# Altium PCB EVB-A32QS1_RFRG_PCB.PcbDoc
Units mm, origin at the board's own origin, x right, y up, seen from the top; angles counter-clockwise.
Board outline 152.4 x 101.6 mm, 4 copper layers (L1 (Signal), L2 (GND), L3 (GND), L4 (Signal)), stack 1.586 mm thick; 35 components, 27 nets, 136 pads, 0 vias.
Unrouted connection lines stored in the file: 88.
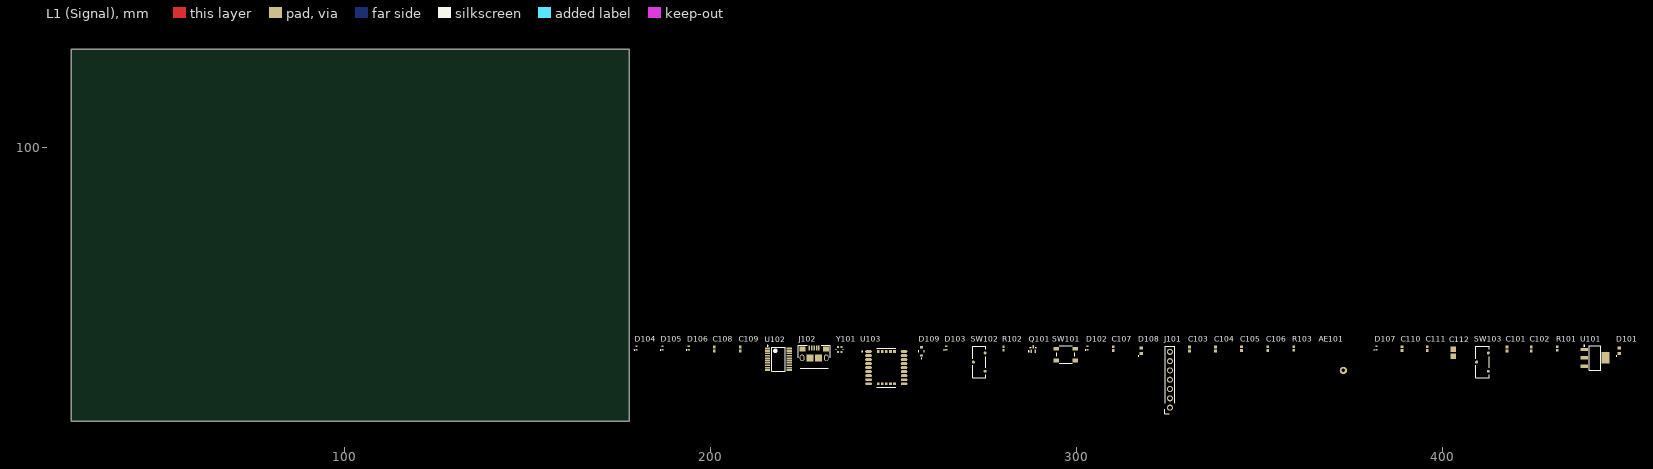
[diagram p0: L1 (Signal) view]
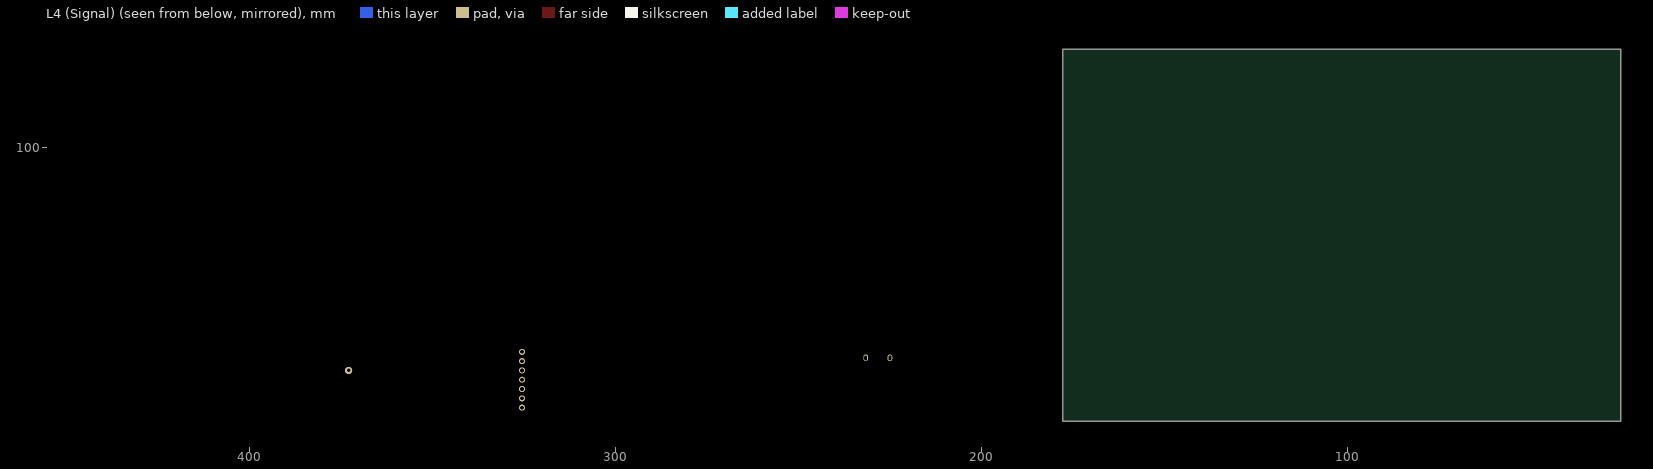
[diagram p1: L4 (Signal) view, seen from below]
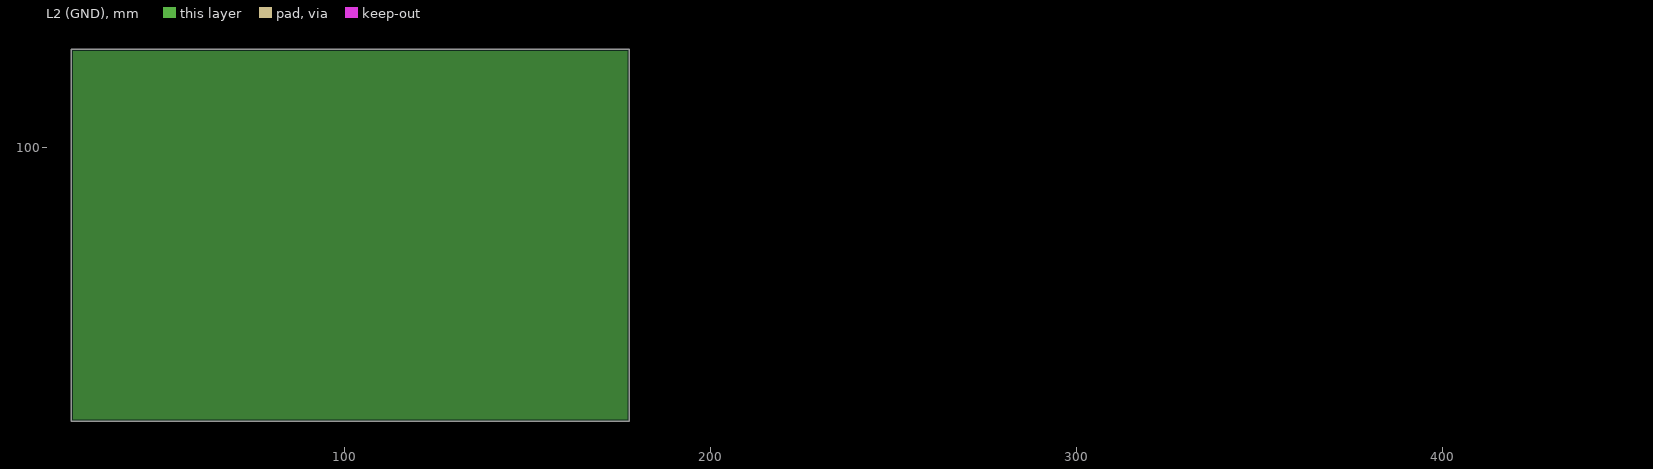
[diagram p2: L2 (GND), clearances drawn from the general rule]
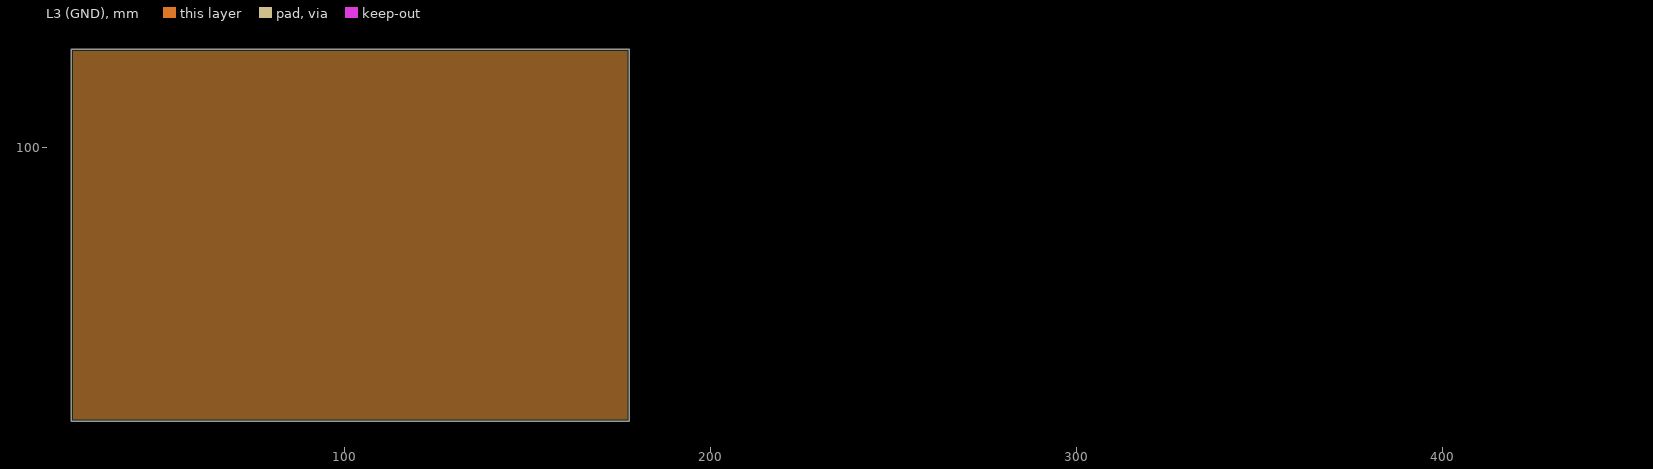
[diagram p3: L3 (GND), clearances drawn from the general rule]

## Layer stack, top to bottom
Top Solder: solder mask 0.0152, JLC-001, Dk 3.8
L1 (Signal): signal copper 0.035
PP1_7628: prepreg 0.2104, Nan Ya Plastics NP-155F 7628, Dk 4.4
L2 (GND): plane copper 0.0152
C_FR4: core 1.065, Nan Ya Plastics NP-155F FR4 / 1-7628, Dk 4.6
L3 (GND): plane copper 0.0152
PP2_7628: prepreg 0.2104, Nan Ya Plastics NP-155F 7628, Dk 4.4
L4 (Signal): signal copper 0.035
Bottom Solder: solder mask 0.0152, JLC-001, Dk 3.8

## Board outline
25.4,25.4 177.8,25.4 177.8,127 25.4,127

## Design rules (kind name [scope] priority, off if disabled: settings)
BoardOutlineClearance [IsText = 'True'] p1: gap=0.3 ignorepadtopadclearanceinfootprint=FALSE
Clearance [All] p1: gap=0.25 ignorepadtopadclearanceinfootprint=FALSE except(0.1: Arc-Arc Arc-Track Track-Track; 0.15: SMDPad-SMDPad; 0.22: Arc-SMDPad Track-SMDPad; 0.27: Arc-Via Arc-Hole Track-Via Track-Hole; 0.5: THPad-THPad)
DiffPairsRouting [InDifferentialPairClass('DIFF_USB')] p1: maxlimit=0.203 minlimit=0.203 mostfreqgap=0.203 toplayer_minwidth=0.286 toplayer_maxwidth=0.286 toplayer_prefwidth=0.286 bottomlayer_minwidth=0.286 bottomlayer_maxwidth=0.286 bottomlayer_prefwidth=0.286 impedanceprofiledriven=TRUE impedanceprofileid={1D80E4EB-765F-47FF-8A09-11E6335E2081} impedanceprofilevalue=90.000000 maxuncoupledlength=12.7
HoleSize NPTHSlotSize [HoleType = 'Slot' && PadIsPlated = 'False'] p1: absolutevalues=TRUE maxlimit=5.6 minlimit=1 maxpercent=80.000 minpercent=20.000
HoleSize PTHSlotSize [HoleType = 'Slot' && PadIsPlated = 'True'] p2: absolutevalues=TRUE maxlimit=5.6 minlimit=0.5 maxpercent=80.000 minpercent=20.000
HoleSize PTHSize [PadIsPlated = 'True'] p3: absolutevalues=TRUE maxlimit=6.35 minlimit=0.2 maxpercent=80.000 minpercent=20.000
HoleSize NPTHSize [PadIsPlated = 'False'] p4: absolutevalues=TRUE maxlimit=6.3 minlimit=0.2 maxpercent=80.000 minpercent=20.000
HoleToHoleClearance [All] p1: gap=0.5 allowstackedmicrovias=TRUE
MinimumAnnularRing PTHSlotMinimumAnnularRing_1 [HoleType = 'Slot' && PadIsPlated = 'True'] p1: minimumring=0.3
MinimumAnnularRing PTHMinimumAnnularRing [PadIsPlated = 'True'] p2: minimumring=0.3
MinimumAnnularRing ViaMinimumAnnularRing [IsVia] p3: minimumring=0.15
MinimumSolderMaskSliver [All] p1: minsoldermaskwidth=0.1
PlaneClearance [All] p1: clearance=0.508
PlaneConnect [All] p1: pad.planeconnectstyle=Relief pad.reliefexpansion=0.508 pad.reliefentries=4 pad.reliefconductorwidth=0.254 pad.reliefairgap=0.254 via.planeconnectstyle=Direct via.reliefexpansion=0.508 via.reliefentries=4 via.reliefconductorwidth=0.254 via.reliefairgap=0.254
PolygonConnect [All] p1: thpad.connectstyle=Relief thpad.reliefconductorwidth=0.254 thpad.reliefentries=4 thpad.polygonreliefangle="90 Angle" thpad.airgapwidth=0.254 smdpad.connectstyle=Relief smdpad.reliefconductorwidth=0.254 smdpad.reliefentries=4 smdpad.polygonreliefangle="90 Angle" smdpad.airgapwidth=0.254 via.connectstyle=Direct via.reliefconductorwidth=0.254 via.reliefentries=4 via.polygonreliefangle="90 Angle" via.airgapwidth=0.254
RoutingVias [All] p1: holewidth=0.3 width=0.7 viastyle="Through Hole" minholewidth=0.2 minwidth=0.5 maxholewidth=0.5 maxwidth=1
SilkToSilkClearance [All] p1: silktosilkclearance=0.3
SilkToSolderMaskClearance [IsPad] p1: minsilkscreentomaskgap=0.15 clearancetoexposedcopper=TRUE
SolderMaskExpansion [All] p1: expansion=0.127 istentingtop=FALSE
SupplyNets "Schematic Supply Nets_6" [InNet('+3V3_GNSS')] p1: voltage=0.000
SupplyNets "Schematic Supply Nets_5" [InNet('VBUS')] p2: voltage=0.000
SupplyNets "Schematic Supply Nets_4" [InNet('GND')] p3: voltage=0.000
SupplyNets "Schematic Supply Nets" [InNet('+3V3')] p4: voltage=0.000
UnRoutedNet [All] p1: checkbadconnections=TRUE
Width AE50 [InNetClass('AE50')] p1: maxlimit=0.349 minlimit=0.349 preferedwidth=0.349 impedanceprofiledriven=TRUE impedanceprofileid={B897B825-96E2-437F-89D6-36A5C33D3538} impedanceprofilevalue=50.000000 minimp=50.000000 maximp=50.000000 favimp=50.000000
Width [All] p2: maxlimit=0.5 minlimit=0.1 preferedwidth=0.25
21 further rules are at their usual default settings.

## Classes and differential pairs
differential pair class DIFF_USB: USB_D
net class AE50: GNSS_RF_IN
differential pair USB_D: +USB_D_P -USB_D_N

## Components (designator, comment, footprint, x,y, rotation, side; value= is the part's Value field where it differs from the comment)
AE101 "YCGA002AA" AE_Quectel_YCGA002AA 372.872,39.243 r0 top
C101 "CC0402MRX5R6BB105" C_Yageo_CC_0402_A 417.576,45.085 r90 top value=1uF
C102 "CC0402MRX5R6BB105" C_Yageo_CC_0402_A 424.18,45.085 r90 top value=1uF
C103 "CC0402MRX5R6BB105" C_Yageo_CC_0402_A 330.835,45.085 r90 top value=1uF
C104 "CC0402KRX7R7BB103" C_Yageo_CC_0402_A 337.947,45.085 r90 top value=10nF
C105 "CL05B104KP5NNNC" C_Samsung_CL_0402_A 345.059,45.212 r90 top value=100nF
C106 "CL05A475MP5NRNC" C_Samsung_CL_0402_A 352.171,45.212 r90 top value=4.7uF
C107 "CL05B104KP5NNNC" C_Samsung_CL_0402_A 310.007,45.212 r90 top value=100nF
C108 "CC0402JRNPO9BN150" C_Yageo_CC_0402_A 201.041,45.085 r90 top value=15pF
C109 "CC0402JRNPO9BN150" C_Yageo_CC_0402_A 208.153,45.085 r90 top value=15pF
C110 "CL05C330JB5NNNC" C_Samsung_CL_0402_A 388.874,45.212 r90 top value=33pF
C111 "CL05B104KP5NNNC" C_Samsung_CL_0402_A 395.732,45.212 r90 top value=100nF
C112 "CL21A106KOQNNNE" C_Samsung_CL_0805_A 402.844,44.069 r90 top value=10uF
D101 "LTST-C190GKT" D_LED_Lite-On_Green_0603_A 448.183,44.577 r90 top
D102 "D5V0F1U2S9-7" D_TVS_Uni_Diodes_SOD-923_B 303.022,45.339 r90 top value=5E-13F
D103 "D5V0F1U2S9-7" D_TVS_Uni_Diodes_SOD-923_B 264.414,45.339 r90 top value=5E-13F
D104 "D5V0F1U2S9-7" D_TVS_Uni_Diodes_SOD-923_B 179.832,45.339 r90 top value=5E-13F
D105 "D5V0F1U2S9-7" D_TVS_Uni_Diodes_SOD-923_B 186.944,45.339 r90 top value=5E-13F
D106 "D5V0F1U2S9-7" D_TVS_Uni_Diodes_SOD-923_B 194.056,45.339 r90 top value=5E-13F
D107 "D5V0F1U2S9-7" D_TVS_Uni_Diodes_SOD-923_B 381.889,45.339 r90 top value=5E-13F
D108 "LTST-C190GKT" D_LED_Lite-On_Green_0603_A 317.627,44.577 r90 top
D109 "ESD7351HT1G" D_TVS_Uni_Onsemi_SOD-323 257.683,44.45 r90 top
J101 "PPPC071LFBN-RC" J_Sullins_01x07_Socket_2.54mm 325.501,36.703 r90 top
J102 "10118193-0001LF" J_USB_Micro-B_Amphenol_10118193-0001LF 228.346,42.672 r0 top
Q101 "DTC043ZEBTL" Q_Rohm_SOT-416FL_B 288.163,45.085 r90 top
R101 "RC0402FR-071KL" R_Yageo_RCL_0402_A 431.292,45.212 r90 top value=1kR
R102 "RC0402FR-0710KL" R_Yageo_RCL_0402_A 280.035,45.212 r90 top value=10kR
R103 "RC0402FR-071KL" R_Yageo_RCL_0402_A 359.283,45.212 r90 top value=1kR
SW101 "PTS647SN50SMTR2LFS" SW_Tactitle_SPST_C&K_PTS647SN50SMTR2LFS 297.053,43.561 r0 top
SW102 "JS102011JCQN" SW_Slide_C&K_JS102011JCQN 273.431,41.529 r90 top
SW103 "JS102011JCQN" SW_Slide_C&K_JS102011JCQN 410.845,41.529 r90 top
U101 "TLV1117LV33DCYR" U_TI_SOT-223_B 441.579,42.672 r0 top
U102 "STM32F070F6P6TR" U_ST_TSSOP20_B 218.567,42.291 r0 top
U103 "LC76GABMD" U_QUECTEL_LC76G 248.031,40.005 r0 top
Y101 "ECS-240-12-37B-CKY-TR" Y_Crystal_GND24_ECS_240-12-37B-CKY-TR 235.331,44.958 r90 top

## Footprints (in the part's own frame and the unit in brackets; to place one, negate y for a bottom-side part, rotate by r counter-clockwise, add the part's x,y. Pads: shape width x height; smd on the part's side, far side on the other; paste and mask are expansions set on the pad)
AE_Quectel_YCGA002AA [mm]
  round 2 hole 0.95: 1(0,0)
  body extent -6,-6 6,6, height 4
C_Samsung_CL_0402_A [mm] "Chip Capacitor, 2-Leads, Body 1.00x0.50mm, IPC Low Density"
  rect 0.76x0.72 smd mask+0.05: 1(-0.49,0) 2(0.49,0)
  body extent -0.53,-0.28 0.53,0.28, height 0.55
C_Samsung_CL_0805_A [mm] "Chip Capacitor, 2-Leads, Body 2.00x1.25mm, IPC Low Density"
  rect 1.45x1.55 smd: 1(-0.95,0) 2(0.95,0)
  body extent -1.07,-0.7 1.07,0.7, height 1.4
C_Yageo_CC_0402_A [mm] "Yageo series CC Chip Capacitor, 2-Leads, Body 1.00x0.50mm, IPC Low Density"
  rect 0.86x0.8 smd mask+0.05: 1(-0.55,0) 2(0.55,0)
  body extent -0.53,-0.28 0.53,0.28, height 0.7
D_LED_Lite-On_Green_0603_A [mm] "Chip Diode, 2-Leads, Body 1.60x0.70mm, IPC Low Density"
  rect 0.85x0.95 smd: 1(-0.75,0) 2(0.75,0)
  silkscreen extent -1.44,0.64 -1.34,0.74, body extent -0.8,-0.4 0.8,0.4, height 0.8
D_TVS_Uni_Diodes_SOD-923_B [mm] "SODFL, 2-Leads, Body 0.60x1.00mm, IPC Medium Density"
  rect 0.4x0.6 smd: 1(-0.45,0) 2(0.45,0)
  silkscreen extent -0.6,0.55 -0.5,0.65, body extent -0.5,-0.33 0.5,0.33, height 0.4
D_TVS_Uni_Onsemi_SOD-323 [mm]
  rect 0.63x0.83 smd: 1(-1.115,0) 2(1.115,0)
  silkscreen extent -2.02,-0.77 0.25,0.77, body extent -1.25,-0.62 1.25,0.62, height 1
J_Sullins_01x07_Socket_2.54mm [mm]
  round 1.65 hole 1.02 mask+0.05: 1(-7.62,0) 2(-5.08,0) 3(-2.54,0) 4(0,0) 5(2.54,0) 6(5.08,0) 7(7.62,0)
  silkscreen extent -9.3,-1.3 9.2,1.4, body extent -9.14,-1.2 9.14,1.34, height 8.5
J_USB_Micro-B_Amphenol_10118193-0001LF [mm] "USB - micro B USB 2.0 Receptacle Connector 5 Position Surface Mount, Right Angle; Through Hole"
  rect 0.4x1.35 smd mask+0.05: 1(-1.3,2.675) 2(-0.65,2.675) 3(0,2.675) 4(0.65,2.675) 5(1.3,2.675)
  rect 1.6x1.4 smd mask+0.05: 6(-3.2,2.45) 7(3.2,2.45)
  rect 1.9x1.9 smd mask+0.05: 8(1.2,0) 9(-1.2,0)
  oval 1.3x1.8 hole 0.7 slot 1.2 at 90 deg mask+0.05: 10(3.3,0) 11(-3.3,0)
  silkscreen extent -4.4,-2.9 4.4,3.5, body extent -3.93,-2.76 3.93,2.95, height 2.81
Q_Rohm_SOT-416FL_B [mm] "SOTFL, 3-Leads, Body 1.60x1.60mm, Pitch 0.50mm, IPC Medium Density"
  rect 0.9x0.4 smd: 1(-0.625,0.5) 2(-0.625,-0.5) 3(0.625,0)
  silkscreen extent -0.75,-0.85 0.48,1.37, body extent -0.8,-0.85 0.8,0.85, height 0.85
R_Yageo_RCL_0402_A [mm] "Yageo series RC_L Chip Resistor, 2-Leads, Body 1.00x0.50mm, IPC Low Density"
  rect 0.65x0.65 smd mask+0.05: 1(-0.5,0) 2(0.5,0)
  body extent -0.53,-0.28 0.53,0.28, height 0.4
SW_Slide_C&K_JS102011JCQN [mm] "Slide Switch SPDT Surface Mount"
  round 0.8 smd mask+0.05: 1(-2.5,-1.6) 2(0,1.6) 3(2.5,-1.6)
  silkscreen extent -4.3,-1.8 4.3,1.8, body extent -4.25,-2 4.25,2, height 5.4
SW_Tactitle_SPST_C&K_PTS647SN50SMTR2LFS [mm] "Tactitle switch SPST-NO 4.5mm x 4.5mm"
  rect 1.55x1 smd mask+0.05: 1(-2.625,1.6) 2(2.625,1.6) 3(-2.625,-1.6) 4(2.625,-1.6)
  silkscreen extent -2.4,-2.4 2.4,2.4, body extent -3.25,-2.25 3.25,2.25, height 5
U_QUECTEL_LC76G [mm]
  oval 1.8x0.8 smd mask+0.05: 1(-4.85,4.4) 2(-4.85,3.3) 3(-4.85,2.2) 4(-4.85,1.1) 5(-4.85,0) 6(-4.85,-1.1) 7(-4.85,-2.2) 8(-4.85,-3.3) 9(-4.85,-4.4) 10(4.85,-4.4) 11(4.85,-3.3) 12(4.85,-2.2) 13(4.85,-1.1) 14(4.85,0) 15(4.85,1.1) 16(4.85,2.2) 17(4.85,3.3) 18(4.85,4.4)
  rect 0.8x0.8 smd mask+0.05: 19(2.2,4.4) 20(1.1,4.4) 21(0,4.4) 22(-1.1,4.4) 23(-2.2,4.4) 24(-2.2,-4.4) 25(-1.1,-4.4) 26(0,-4.4) 27(1.1,-4.4) 28(2.2,-4.4)
  silkscreen extent -6.72,-5.3 2.6,5.3, body extent -4.85,-5.05 4.85,5.05, height 2.66
U_ST_TSSOP20_B [mm] "TSOP, 20-Leads, Body 6.50x4.40mm, Pitch 0.65mm, IPC Medium Density"
  rect 1.4x0.45 smd mask+0.05: 1(-2.95,2.925) 2(-2.95,2.275) 3(-2.95,1.625) 4(-2.95,0.975) 5(-2.95,0.325) 6(-2.95,-0.325) 7(-2.95,-0.975) 8(-2.95,-1.625) 9(-2.95,-2.275) 10(-2.95,-2.925) 11(2.95,-2.925) 12(2.95,-2.275) 13(2.95,-1.625) 14(2.95,-0.975) 15(2.95,-0.325) 16(2.95,0.325) 17(2.95,0.975) 18(2.95,1.625) 19(2.95,2.275) 20(2.95,2.925)
  silkscreen extent -3.07,-3.3 1.85,3.82, body extent -3.2,-3.25 3.2,3.25, height 1.2
U_TI_SOT-223_B [mm] "SOT223, 4-Leads, Body 6.50x7.00mm (avg), Pitch 2.30mm, IPC Medium Density"
  rect 2.15x0.9 smd: 1(-2.925,2.3) 2(-2.925,0) 3(-2.925,-2.3)
  rect 2.15x3.2 smd: 4(2.925,0)
  silkscreen extent -3.05,-3.35 1.55,3.42, body extent -3.5,-3.35 3.5,3.35, height 1.8
Y_Crystal_GND24_ECS_240-12-37B-CKY-TR [mm]
  rect 0.65x0.55 smd mask+0.05: 1(-0.675,-0.525) 2(0.675,-0.525) 3(0.675,0.525) 4(-0.675,0.525)
  silkscreen extent -0.1,-0.9 0.1,0.9, body extent -1,-0.8 1,0.8, height 0.51

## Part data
AE101: library part CMP-00025-00001-1, "Antenna Module Linear 1602MHz", Frequency (Center/Band)=1.5825GHz, Frequency Group="UHF (1GHz ~ 2GHz)", Frequency Range="1.559GHz ~ 1.606GHz", Manufacturer=Quectel
C101 C102 C103: library part CMP-001-00016-11, "Multilayer Ceramic Capacitor, 1 uF, 50 V, ± 10%, X5R, 0402 [1005 Metric]", Case Code (Imperial)=0402, Case Code (Metric)=1005, Dielectric=X5R, LCSC Part Number=C113791, Max Operating Temperature=85°C, Min Operating Temperature=-55°C, Temperature Coefficient=30ppm/°C, Tolerance=20%, Voltage Rating=10V
C104: library part CMP-001-00029-1, "Multilayer Ceramic Capacitor, 0.01 uF, 16 V, ± 10%, X7R, 0402 [1005 Metric]", Case Code (Imperial)=0402, Case Code (Metric)=1005, Dielectric=X7R, Insulation Resistance=10GR, Max Operating Temperature=125°C, Min Operating Temperature=-55°C, Package Quantity=1, Temperature Coefficient=30ppm/°C, Tolerance=10%, Voltage Rating=16V
C105 C107 C111: library part CMP-001-00023-3, "Multilayer Ceramic Capacitor, 0.1 uF, 10 V, ± 10%, X7R, 0402 [1005 Metric]", Case Code (Imperial)=0402, Case Code (Metric)=1005, Dielectric=X7R, Max Operating Temperature=125°C, Min Operating Temperature=-55°C, Package Quantity=1, Tolerance=10%, Voltage Rating=10V
C106: library part CMP-001-00024-3, "Multilayer Ceramic Capacitor, 4.7 uF, 10 V, ± 20%, X5R, 0402 [1005 Metric]", Case Code (Imperial)=0402, Case Code (Metric)=1005, Dielectric=X5R, Max Operating Temperature=85°C, Min Operating Temperature=-55°C, Tolerance=20%, Voltage Rating=10V
C108 C109: library part CMP-001-00017-14, "Multilayer Ceramic Capacitor, 15 pF, 10 V, ± 5%, X7R, 0402 [1005 Metric]", Case Code (Imperial)=0402, Case Code (Metric)=1005, Dielectric=C0G, Dielectric Material=Ceramic, Insulation Resistance=100GR, Max Operating Temperature=125°C, Min Operating Temperature=-55°C, Package Quantity=1, Temperature Coefficient=30ppm/°C, Tolerance=5%, Voltage=50V
C110: library part CMP-001-00030-2, "Multilayer Ceramic Capacitor, 33 pF, 50 V, ± 5%, C0G (NP0), 0402 [1005 Metric]", Case Code (Imperial)=0402, Case Code (Metric)=1005, Dielectric=C0G, Max Operating Temperature=125°C, Min Operating Temperature=-55°C, Package Quantity=1, Temperature Coefficient=300ppm/°C, Tolerance=5%, Voltage=50V
C112: library part CMP-001-00022-4, "Multilayer Ceramic Capacitor, 10 uF, 16 V, ± 10%, X5R, 0805 [2012 Metric]", Case Code (Imperial)=0805, Case Code (Metric)=2012, Dielectric=X7R, Max Operating Temperature=85°C, Min Operating Temperature=-55°C, Package Quantity=1, Tolerance=10%, Voltage=16V
D101 D108: library part CMP-007-00001-3, "LED Uni-Color Green 565nm 2-Pin Chip LED T/R", Case Code (Imperial)=0603, Case Code (Metric)=1608, Color=Green, Forward Current=30mA, Forward Voltage=2.1V, Lens Color=Colorless, Max Operating Temperature=85°C, Min Operating Temperature=-55°C, Package Quantity=1, Power Dissipation=100mW, Reverse Voltage=5V, Test Current=10mA, Voltage=2V
D102 D103 D104 D105 D106 D107: library part CMP-004-00007-2, "Diode TVS Dual Uni-Dir 5.5V 250000W 2-Pin SOD-923 T/R", Breakdown Voltage=6V, Case/Package=SOD-923-2, Clamping Voltage=10V, Max Operating Temperature=150°C, Max Power Dissipation=250mW, Max Reverse Leakage Current=100nA, Max Surge Current=1.5A, Min Operating Temperature=-65°C, Package Quantity=10000, Peak Pulse Power=250kW, Power Line Protection=Yes, Reverse Standoff Voltage=5.5V
D109: library part CMP-004-00006-1, "TVSDIODE3.3VWMSOD-323", Case/Package=SOD, Max Operating Temperature=150°C, Min Breakdown Voltage=5V, Min Operating Temperature=-55°C, Package Quantity=3000, Power Line Protection=No, Reverse Standoff Voltage=3.3V
J101: library part CMP-002-00007-1, "Conn Hdr 7POS 0.1 Gold Pcb", Flammability Rating="UL94 V-0", Insulation Color=Black, Max Operating Temperature=105°C, Min Operating Temperature=-40°C, Voltage Rating=250V
J102: library part CMP-002-00002-12, "Usb Connector, 5 Contact(S), Female, Right Angle, Surface Mount Terminal, Locking, Receptacle", Color=Black, Current Rating=1.8A, Flammability Rating="UL94 V-0", Insulation Resistance=1GR, Max Operating Temperature=85°C, Max Voltage Rating (AC)=100V, Min Operating Temperature=-55°C, Package Quantity=1200
Q101: library part CMP-013-00001-1, "TRANS PREBIAS NPN 50V EMT3F", Clock Frequency=250MHz, Collector Emitter Breakdown Voltage=50V, Collector-emitter Voltage-Max=150mV, Continuous Collector Current=100mA, Max Operating Temperature=150°C, Max Power Dissipation=150mW, Min Operating Temperature=-55°C, Output Voltage=50mV, Package Quantity=3000
R101 R103: library part CMP-009-00002-11, "SMD Chip Resistor, 1 kOhm, ± 1%, 62.5 mW, 0402 [1005 Metric], Thick Film, General Purpose", Case Code (Imperial)=0402, Case Code (Metric)=1005, Max Operating Temperature=155°C, Max Power Dissipation=63mW, Min Operating Temperature=-55°C, Power Rating=62.5mW, Resistance Tolerance=1%, Resistor Type="Thick Film", Temperature Coefficient=100ppm/°C, Voltage Rating=50V
R102: library part CMP-009-00003-11, "SMD Chip Resistor, 10 kOhm, ± 1%, 62.5 mW, 0402 [1005 Metric], Thick Film, General Purpose", Case Code (Imperial)=0402, Case Code (Metric)=1005, Max Operating Temperature=155°C, Max Power Dissipation=63mW, Min Operating Temperature=-55°C, Power Rating=62.5mW, Resistance Tolerance=1%, Resistor Type="Thick Film", Temperature Coefficient=100ppm/°C, Voltage Rating=50V
SW101: library part CMP-011-00000-13, "Switch Tactile N.O. SPST Round Button Gull Wing 0.05A 12VDC 100000Cycles 0.98N SMD T/R", Max Operating Temperature=70°C, Min Operating Temperature=-20°C, Operating Force=100gf, Ratings=IP40
SW102 SW103: library part CMP-011-00001-10, "JS Series Sub-Miniature Slide Switch SPDT On-On Top Slide 0.3A 6VDC J-Lead Surface Mount T/R", Max Operating Temperature=85°C, Min Operating Temperature=-40°C, Voltage Rating (DC)=6V
U101: library part CMP-019-00002-2, "LDO Regulator Pos 3.3V 1A 4-Pin(3+Tab) SOT-223 T/R", Case/Package=SOT-223-4, Dropout Voltage=570mV, Max Operating Temperature=125°C, Max Output current=1A, Max Output Voltage=3.3V, Max Supply Voltage=5.5V, Min Input Voltage=2V, Min Operating Temperature=-40°C, Operating Supply Current=50uA, Package Quantity=2500, Power Supply Rejection Ratio (PSRR)=75dB
U102: library part CMP-020-00001-4, "IC MCU 32BIT 32KB FLASH 20TSSOP", Case/Package=TSSOP, Max Operating Temperature=85°C, Min Operating Temperature=-40°C
U103: library part CMP-00025-00000-4, "Navigation BeiDou, Galileo, GLONASS, GPS, GNSS Transceiver Module 1.561GHz, 1.575GHz, 1.602GHz Antenna Not Included Surface Mount", Frequency="1.561GHz, 1.575GHz, 1.602GHz", Package="28-SMD Module", Supply Voltage="2.55V ~ 3.6V"
Y101: library part CMP-003-00000-11, "Crystal 24MHz ±10ppm (Tol) ±10ppm (Stability) 12pF FUND 50Ohm 4-Pin Mini-CSMD T/R", Case/Package="4-SMD, No Lead", Frequency=24MHz, Load Capacitance=12pF

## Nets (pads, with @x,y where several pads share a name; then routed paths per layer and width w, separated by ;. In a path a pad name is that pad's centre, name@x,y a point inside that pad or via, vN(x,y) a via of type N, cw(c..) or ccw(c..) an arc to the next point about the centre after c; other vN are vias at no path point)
+3V3: C102.2 C103.2 C104.2 C105.2 C106.2 D101.2 J101.1 R103.2 SW102.3 SW103.3 U101.2 U101.4 U102.5 U102.16
+3V3_GNSS: C110.2 C111.2 C112.2 D107.1 SW103.2 U103.6 U103.8
BOOT0: R102.2 U102.1
GND: C101.1 C102.1 C103.1 C104.1 C105.1 C106.1 C107.1 C108.1 C109.1 C110.1 C111.1 C112.1 D102.2 D103.2 D104.2 D105.2 D106.2 D107.2 D109.2 J101.2 J102.5 Q101.2 R101.1 SW101.3 SW101.4 SW102.1 SW103.1 U101.1 U102.15 U103.1 U103.10 U103.12 U103.28 Y101.2 Y101.4
GNSS_1PPS: Q101.1 U103.4
GNSS_3D: U102.10 U103.23
GNSS_GEO: U102.6 U103.21
GNSS_JAM: U102.7 U103.22
GNSS_NRST: U102.14 U103.9
GNSS_RF_IN: AE101.1 D109.1 U103.11
GNSS_RXD: U102.8 U103.3
GNSS_TXD: U102.9 U103.2
NetD101_1: D101.1 R101.2
NetD108_1: D108.1 Q101.3
NetD108_2: D108.2 R103.1
NRST: C107.2 D102.1 SW101.1 SW101.2 U102.4
OSC_IN: C108.2 U102.2 Y101.1
OSC_OUT: C109.2 U102.3 Y101.3
PA5: J101.5 U102.11
PA6: J101.6 U102.12
PA7: J101.7 U102.13
SW_BOOT0: D103.1 R102.1 SW102.2
SW_CLK: J101.4 U102.20
SW_IO: J101.3 U102.19
USB_D_N: D105.1 J102.2 U102.17
USB_D_P: D106.1 J102.3 U102.18
VBUS: C101.2 D104.1 J102.1 U101.3
pads on no net: J102.4 J102.6 J102.7 J102.8 J102.9 J102.10 J102.11 U103.5 U103.7 U103.13 U103.14 U103.15 U103.16 U103.17 U103.18 U103.19 U103.20 U103.24 U103.25 U103.26 U103.27

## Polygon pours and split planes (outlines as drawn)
no net on L2 (GND) (split plane): 177.29,25.91 25.91,25.91 25.91,126.49 177.29,126.49
no net on L3 (GND) (split plane): 177.29,25.91 25.91,25.91 25.91,126.49 177.29,126.49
